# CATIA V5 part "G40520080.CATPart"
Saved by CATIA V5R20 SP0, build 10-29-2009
Part number: G40520080
Revision: 6
Definition: design
Nomenclature: G40520080
Source: made
Description: NOT SPECIFIED
Bounding box of the stored display mesh (mm): x -40 to 40, y -10 to 10, z -20 to 0
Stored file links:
  C:\Users\Raffaele\Desktop\3D X SITO CF\BOLEX\29-GUIDE STRIP REF 405\G40520080.CATPart
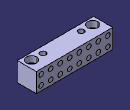
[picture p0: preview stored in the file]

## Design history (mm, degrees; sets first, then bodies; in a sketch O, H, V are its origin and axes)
Body1 "MANIFOLD_SOLID_BREP #2998" (main body)
  Solid1: solid without history
Body2 "MANIFOLD_SOLID_BREP #3136"
  Solid2: solid without history
Body3 "MANIFOLD_SOLID_BREP #3248"
  Solid3: solid without history
Body4 "MANIFOLD_SOLID_BREP #3360"
  Solid4: solid without history
Body5 "MANIFOLD_SOLID_BREP #3472"
  Solid5: solid without history
Body6 "MANIFOLD_SOLID_BREP #3584"
  Solid6: solid without history
Body7 "MANIFOLD_SOLID_BREP #3696"
  Solid7: solid without history
Body8 "MANIFOLD_SOLID_BREP #3808"
  Solid8: solid without history
Body9 "MANIFOLD_SOLID_BREP #3920"
  Solid9: solid without history
Body10 "MANIFOLD_SOLID_BREP #4032"
  Solid10: solid without history
Body11 "MANIFOLD_SOLID_BREP #4144"
  Solid11: solid without history
Body12 "MANIFOLD_SOLID_BREP #4256"
  Solid12: solid without history
Body13 "MANIFOLD_SOLID_BREP #4368"
  Solid13: solid without history
Body14 "MANIFOLD_SOLID_BREP #4480"
  Solid14: solid without history
Body15 "MANIFOLD_SOLID_BREP #4592"
  Solid15: solid without history
Body16 "MANIFOLD_SOLID_BREP #4704"
  Solid16: solid without history
Body17 "MANIFOLD_SOLID_BREP #4842"
  Solid17: solid without history
Body18 "MANIFOLD_SOLID_BREP #4980"
  Solid18: solid without history
Body19 "MANIFOLD_SOLID_BREP #5118"
  Solid19: solid without history
Body20 "MANIFOLD_SOLID_BREP #5256"
  Solid20: solid without history
Body21 "MANIFOLD_SOLID_BREP #5394"
  Solid21: solid without history
Body22 "MANIFOLD_SOLID_BREP #5532"
  Solid22: solid without history
Body23 "MANIFOLD_SOLID_BREP #5644"
  Solid23: solid without history
Body24 "MANIFOLD_SOLID_BREP #5756"
  Solid24: solid without history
